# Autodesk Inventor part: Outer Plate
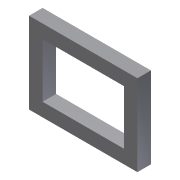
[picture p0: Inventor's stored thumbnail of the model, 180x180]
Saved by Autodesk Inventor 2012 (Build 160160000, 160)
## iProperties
Created: 2010-04
Part Number: Outer Plate
Document SubType Name: Modeling
Designer: CADSoft
Density: 1 g/cm^3
Material: Default
Author: CADSoft
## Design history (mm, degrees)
sketch "Sketch1"
  geometry: L1 (-40, 30)-(40, 30); L2 (40, 30)-(40, -30); L3 (40, -30)-(-40, -30); L4 (-40, -30)-(-40, 30); L5 (-30, 20)-(30, 20); L6 (30, 20)-(30, -20); L7 (30, -20)-(-30, -20); L8 (-30, -20)-(-30, 20); 1 further point
  constraints: 16 end point, 4 parallel, 2 horizontal, 2 perpendicular
  dimensions: "d0" = 80 distance of L1.start L1.end; "d1" = 60 distance of L5.start L5.end; "d2" = 10 distance between parallel lines of L4 L8; "d3" = 10 distance between parallel lines of L1 L5; "d4" = 40 distance of L7.end L5.start; "d5" = 60 distance of L3.end L1.start
extrude "Extrusion1" new body sketch "Sketch1" distance "d8" = 10; taper "d9" = 0 deg
body "Solid1"
